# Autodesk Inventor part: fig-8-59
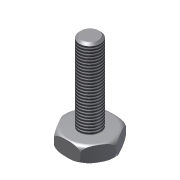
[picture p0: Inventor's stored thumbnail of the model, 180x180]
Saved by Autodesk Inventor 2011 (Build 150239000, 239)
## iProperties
Shininess: 77.0
Length Units: 11269
Angle Units: 11279
Time Units: 11290
Mass Units: 11283
Length Display Precision: 3
Angle Display Precision: 2
Created: 2002-01
Part Number: fig-8-59
Document SubType Name: Modeling
Designer: ***
Density: 1 g/cm^3
Density: 0.0
Volumn: 0.0
Area: 0.0
PropertySet Name: Model Information
Control State: 0
Master: False
Checked Out: False
Author: ***
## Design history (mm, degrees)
sketch "Sketch1"
  geometry: C1 r 25 at (0, 0)
  constraints: 1 centre point
  dimensions: "d0" = 50 diameter of C1
extrude "Extrusion1" new body sketch "Sketch1" distance "d1" = 15; taper "d2" = 0 deg
fillet "Fillet1" dims "d3" = 5
sketch "Sketch2"
  geometry: L1 (25.058, 0)-(12.529, -21.701); L2 (12.529, -21.701)-(-12.529, -21.701); L3 (-12.529, -21.701)-(-25.058, 0); L4 (-25.058, 0)-(-12.529, 21.701); L5 (-12.529, 21.701)-(12.529, 21.701); L6 (12.529, 21.701)-(25.058, 0); 1 further point
  constraints: 12 end point, 11 other
extrude "Extrusion2" sketch "Sketch2" stored distance "d4" = 15; taper "d5" = 0 deg
sketch "Sketch3"
  geometry: C1 r 10.044 at (0, 0); 1 further point
  constraints: 1 centre point, 1 coincident
extrude "Extrusion3" join sketch "Sketch3" distance "d6" = 75; taper "d7" = 0 deg
chamfer "Chamfer1" distance "d8" = 2; stored, may be unused: second distance "d9" = 2, angle "d16" = 45 deg
thread "Thread3" dims "d14" = 30, "d15" = 0
body "Solid1"
